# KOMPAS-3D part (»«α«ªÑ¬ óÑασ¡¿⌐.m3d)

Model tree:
1. Эскиз:1
2. Операция выдавливания:1
     Расстояние 1 = 8
3. Эскиз:2
4. Операция выдавливания:2
     Расстояние 1 = 1
5. Эскиз:3
6. Операция выдавливания:3
     Расстояние 1 = 2.5; Угол 1 = 8
7. Эскиз:4
8. Вырезать элемент выдавливания:1
     Расстояние 1 = 20
9. Эскиз:5
10. Вырезать элемент выдавливания:2
     Расстояние 1 = 3; Угол 1 = 19
11. Скругление:1
     Радиус = 1
12. Скругление:2
     Радиус = 1
13. Скругление:3
     Радиус = 1
14. Эскиз:6
15. Эскиз:7
16. Вырезать элемент выдавливания:3
     Расстояние 1 = 2.5
17. Эскиз:8
18. Вырезать элемент выдавливания:4
     Расстояние 1 = 42
19. Операция выдавливания:4
     Расстояние 1 = 0.8; Расстояние 2 = 1.5
